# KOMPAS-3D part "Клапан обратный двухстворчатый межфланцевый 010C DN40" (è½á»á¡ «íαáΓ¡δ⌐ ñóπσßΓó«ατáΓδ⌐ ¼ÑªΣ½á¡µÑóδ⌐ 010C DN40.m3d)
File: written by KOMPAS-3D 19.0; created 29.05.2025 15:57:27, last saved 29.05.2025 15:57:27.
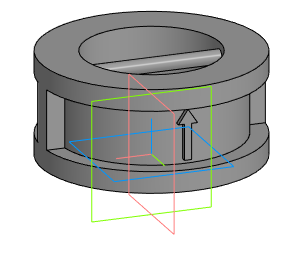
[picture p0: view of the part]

Document properties: Полное имя файла: E:\Dendor Работа Сачек\3D для проекитирвщиков\5.2 Тип 010C, 010C.Y Клапан обратный двухстворчатый межфланцевый\stp_Клапан обратный двухстворчатый межфланцевый 010C\Клапан обратный двухстворчатый межфланцевый 010C DN40.m3d

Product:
- Part/product: Клапан обратный двухстворчатый межфланцевый 010C DN40

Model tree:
1. Операция без истории:1  (labels: Клапан обратный двухстворчатый межфланцевый 010C DN40)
